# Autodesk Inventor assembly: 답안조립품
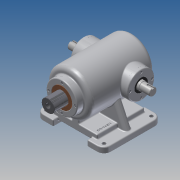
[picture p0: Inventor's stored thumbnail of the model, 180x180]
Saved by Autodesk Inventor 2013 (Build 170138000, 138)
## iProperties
Created: 2014-12
Part Number: 답안조립품
Document SubType Name: Assembly
Designer: CAD-B22
Mass: 8641.3 g
Surface Area: 4328.77 cm^2
Volume: 2314.18 cm^3
Density: 3.73407 g/cm^3
Author: CAD-B22
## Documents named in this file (13)
- C:\Users\CAD-B22\Desktop\341228V1003\답안조립품.iam
- C:\Users\CAD-B22\Desktop\341228V1003\341228V1003\본체.ipt
- C:\Users\CAD-B22\Desktop\341228V1003\341228V1003\M4x0.7.ipt
- C:\Users\CAD-B22\Desktop\341228V1003\341228V1003\베어링 6205.ipt
- 베어링 6205.ipt
- C:\Users\CAD-B22\Desktop\341228V1003\341228V1003\부시.ipt
- C:\Users\CAD-B22\Desktop\341228V1003\341228V1003\슬라이드 커버.ipt
- C:\Users\CAD-B22\Desktop\341228V1003\341228V1003\슬라이드.ipt
- C:\Users\CAD-B22\Desktop\341228V1003\341228V1003\오일실.ipt
- 오일실.ipt
- C:\Users\CAD-B22\Desktop\341228V1003\341228V1003\축 커버.ipt
- C:\Users\CAD-B22\Desktop\341228V1003\341228V1003\편심축.ipt
- C:\Users\CAD-B22\Desktop\341228V1003\스프링.ipt
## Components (12 placed, 1 different names)
1. M4x0.7:1 — 각도:1
2. M4x0.7:2
3. M4x0.7:3
4. M4x0.7:4
5. M4x0.7:5 — 각도:2
6. M4x0.7:6
7. M4x0.7:7
8. M4x0.7:8
9. M4x0.7:9 — 각도:3
10. M4x0.7:10
11. M4x0.7:11
12. M4x0.7:12
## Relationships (3: Angle 3)
- 각도:1 [Angle]: M4x0.7:1
- 각도:2 [Angle]: M4x0.7:5
- 각도:3 [Angle]: M4x0.7:9
